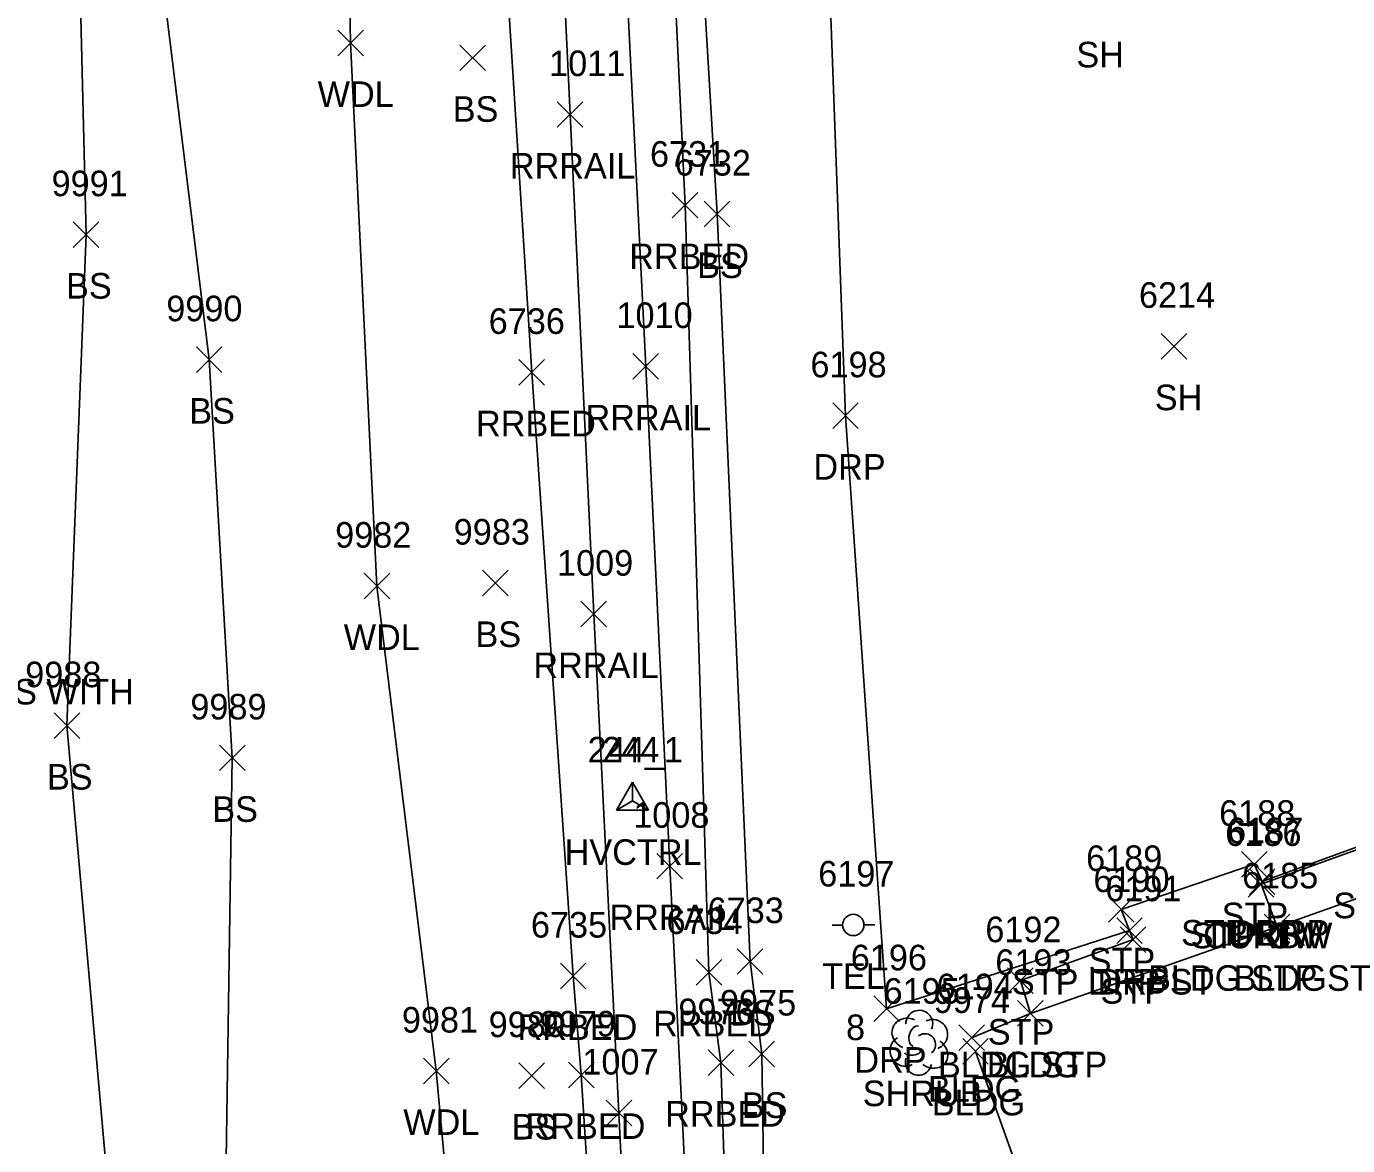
# Model space of a CAD drawing. Extents: x 1769141 to 1770817, y 735471 to 742405.
# Drawn here: x 1770145.7 to 1770248.9, y 740504.9 to 740592.3 of the extents above; entities that cross this region are included whole.
import ezdxf

# ---------------------------------------------------------------- set-up
doc = ezdxf.new("R2010")
doc.units = 0
for name, color, linetype in [('C_A', 7, 'Continuous'), ('C_I', 7, 'Continuous'), ('CPSM', 7, 'Continuous'), ('L_A', 7, 'Continuous'), ('L_I', 7, 'Continuous'), ('L_TIC', 7, 'Continuous'), ('LAWA', 7, 'Continuous'), ('LBC', 7, 'Continuous'), ('LBF', 7, 'Continuous'), ('LELB', 7, 'Continuous'), ('LSH', 7, 'Continuous'), ('R_A', 7, 'Continuous'), ('R_C', 7, 'Continuous'), ('R_I', 7, 'Continuous'), ('R_TIC', 7, 'Continuous'), ('RC', 7, 'Continuous'), ('RDP', 7, 'Continuous'), ('RR', 7, 'Continuous'), ('RRB', 7, 'Continuous'), ('U_A', 7, 'Continuous'), ('U_C', 7, 'Continuous'), ('U_I', 7, 'Continuous'), ('UP', 7, 'Continuous')]:
    doc.layers.add(name, color=color, linetype=linetype)

msp = doc.modelspace()

# ---------------------------------------------------------------- linework, layer by layer
at = {"layer": 'CPSM'}
for p, q in [((1770191.81, 740531.11), (1770193.06, 740533.28)), ((1770191.81, 740531.11), (1770193.06, 740533.28)), ((1770194.31, 740531.11), (1770193.06, 740533.28)), ((1770193.06, 740531.83), (1770193.06, 740533.28)), ((1770194.31, 740531.11), (1770193.06, 740533.28)), ((1770193.06, 740531.83), (1770193.06, 740533.28)), ((1770191.81, 740531.11), (1770193.06, 740531.83)), ((1770191.81, 740531.11), (1770193.06, 740531.83)), ((1770193.06, 740531.83), (1770193.06, 740531.83)), ((1770193.06, 740531.83), (1770194.31, 740531.11)), ((1770193.06, 740531.83), (1770193.06, 740531.83)), ((1770193.06, 740531.83), (1770194.31, 740531.11)), ((1770191.81, 740531.11), (1770194.31, 740531.11)), ((1770191.81, 740531.11), (1770194.31, 740531.11))]:
    msp.add_line(p, q, dxfattribs=at)
at = {"layer": 'L_TIC'}
for points in [[(1770170.04, 740590.04), (1770172.04, 740592.04)], [(1770172.04, 740590.04), (1770170.04, 740592.04)], [(1770179.57, 740588.88), (1770181.57, 740590.88)], [(1770181.57, 740588.88), (1770179.57, 740590.88)], [(1770198.66, 740576.68), (1770200.66, 740578.68)], [(1770200.66, 740576.68), (1770198.66, 740578.68)], [(1770149.37, 740575.07), (1770151.37, 740577.07)], [(1770151.37, 740575.07), (1770149.37, 740577.07)], [(1770234.35, 740566.35), (1770236.35, 740568.35)], [(1770236.35, 740566.35), (1770234.35, 740568.35)], [(1770158.99, 740565.3), (1770160.99, 740567.3)], [(1770160.99, 740565.3), (1770158.99, 740567.3)], [(1770172.09, 740547.61), (1770174.09, 740549.61)], [(1770174.09, 740547.61), (1770172.09, 740549.61)], [(1770181.35, 740547.85), (1770183.35, 740549.85)], [(1770183.35, 740547.85), (1770181.35, 740549.85)], [(1770147.88, 740536.71), (1770149.88, 740538.71)], [(1770149.88, 740536.71), (1770147.88, 740538.71)], [(1770160.79, 740534.19), (1770162.79, 740536.19)], [(1770162.79, 740534.19), (1770160.79, 740536.19)], [(1770240.61, 740525.88), (1770242.61, 740527.88)], [(1770242.61, 740525.88), (1770240.61, 740527.88)], [(1770241.15, 740524.31), (1770243.15, 740526.31)], [(1770243.15, 740524.31), (1770241.15, 740526.31)], [(1770241.23, 740524.52), (1770243.23, 740526.52)], [(1770243.23, 740524.52), (1770241.23, 740526.52)], [(1770230.23, 740522.35), (1770232.23, 740524.35)], [(1770232.23, 740522.35), (1770230.23, 740524.35)], [(1770230.87, 740520.7), (1770232.87, 740522.7)], [(1770232.87, 740520.7), (1770230.87, 740522.7)], [(1770242.4, 740520.99), (1770244.4, 740522.99)], [(1770244.4, 740520.99), (1770242.4, 740522.99)], [(1770242.4, 740520.99), (1770244.4, 740522.99)], [(1770244.4, 740520.99), (1770242.4, 740522.99)], [(1770231.15, 740519.99), (1770233.15, 740521.99)], [(1770233.15, 740519.99), (1770231.15, 740521.99)], [(1770201.23, 740518.28), (1770203.23, 740520.28)], [(1770203.23, 740518.28), (1770201.23, 740520.28)], [(1770222.35, 740516.79), (1770224.35, 740518.79)], [(1770224.35, 740516.79), (1770222.35, 740518.79)], [(1770223.13, 740514.23), (1770225.13, 740516.23)], [(1770225.13, 740514.23), (1770223.13, 740516.23)], [(1770223.13, 740514.23), (1770225.13, 740516.23)], [(1770225.13, 740514.23), (1770223.13, 740516.23)], [(1770218.54, 740512.33), (1770220.54, 740514.33)], [(1770220.54, 740512.33), (1770218.54, 740514.33)], [(1770218.84, 740511.26), (1770220.84, 740513.26)], [(1770220.84, 740511.26), (1770218.84, 740513.26)], [(1770202.15, 740511.06), (1770204.15, 740513.06)], [(1770204.15, 740511.06), (1770202.15, 740513.06)], [(1770176.73, 740509.73), (1770178.73, 740511.73)], [(1770178.73, 740509.73), (1770176.73, 740511.73)], [(1770184.17, 740509.37), (1770186.17, 740511.37)], [(1770186.17, 740509.37), (1770184.17, 740511.37)]]:
    msp.add_lwpolyline(points, dxfattribs=at)
at = {"layer": 'LAWA'}
for points in [[(1770171.04, 740591.04), (1770170.45, 740620.93)], [(1770183.2, 740359.32), (1770182.39, 740388.64), (1770182, 740440), (1770181.07, 740474.45), (1770177.73, 740510.73), (1770173.09, 740548.61), (1770171.04, 740591.04)]]:
    msp.add_lwpolyline(points, dxfattribs=at)
at = {"layer": 'LBC'}
for points in [[(1770225.6, 740472.93), (1770279.13, 740491.75), (1770265.37, 740529.79), (1770243.4, 740521.99), (1770224.13, 740515.23), (1770219.54, 740513.33)], [(1770225.27, 740474.05), (1770218.82, 740491.55), (1770226.07, 740494.84), (1770219.84, 740512.26)]]:
    msp.add_lwpolyline(points, dxfattribs=at)
at = {"layer": 'LBF'}
msp.add_lwpolyline([(1770243.4, 740521.99), (1770242.15, 740525.31), (1770242.23, 740525.52), (1770241.61, 740526.88), (1770231.23, 740523.35), (1770231.87, 740521.7), (1770232.15, 740520.99), (1770223.35, 740517.79), (1770224.13, 740515.23)], dxfattribs=at)
at = {"layer": 'LELB'}
for points in [[(1770192.19, 740728.03), (1770194.1, 740678.66), (1770196.52, 740630.7), (1770199.66, 740577.68), (1770202.23, 740519.28)], [(1770167.07, 740363.73), (1770164.66, 740417.49), (1770161.1, 740489.86), (1770161.79, 740535.19), (1770159.99, 740566.3), (1770156.13, 740597.65), (1770156.76, 740657.51)], [(1770157.79, 740363.98), (1770157.08, 740418.77), (1770153.72, 740483.23), (1770148.88, 740537.71), (1770150.37, 740576.07), (1770149.56, 740610.02), (1770143.11, 740653.52)], [(1770203.15, 740512.06), (1770202.23, 740519.28)], [(1770211.26, 740331.68), (1770209.42, 740362.93), (1770207.28, 740387.78), (1770204.09, 740437.38), (1770203.7, 740475.25), (1770203.15, 740512.06)]]:
    msp.add_lwpolyline(points, dxfattribs=at)
at = {"layer": 'LSH'}
msp.add_line((1770215.4, 740512.98), (1770215.4, 740512.98), dxfattribs=at)
msp.add_line((1770215.4, 740512.98), (1770215.4, 740512.98), dxfattribs=at)
msp.add_arc((1770215.45, 740514.42), 1.05, 335.5272, 180.9563, dxfattribs=at)
for centre, major_axis, ratio, start_param, end_param in [((1770214.61, 740513.65), (1.21, -0.51), 0.895232, 1.570796, 4.712389), ((1770215.19, 740513.44), (-0.208, -0.792), 0.645439, 3.141593, 6.283185), ((1770216.44, 740513.56), (-1.14, -0.48), 0.949671, 1.570796, 4.712389), ((1770214.32, 740512.27), (0.58, -1.04), 0.959034, 3.141593, 6.283185), ((1770215.9, 740512.81), (-0.5, 0.667), 0.989748, 3.141593, 6.283185), ((1770214.94, 740512.23), (-0.625, -0.083), 0.423636, 0, 3.141593), ((1770216.4, 740512.15), (-1.09, 0.79), 0.841452, 1.570796, 4.712389), ((1770215.4, 740511.48), (0.26, 1.06), 0.942809, 1.570796, 4.712389)]:
    msp.add_ellipse(centre, major_axis=major_axis, ratio=ratio, start_param=start_param, end_param=end_param, dxfattribs=at)
at = {"layer": 'R_TIC'}
for points in [[(1770187.18, 740584.45), (1770189.18, 740586.45)], [(1770189.18, 740584.45), (1770187.18, 740586.45)], [(1770196.16, 740577.37), (1770198.16, 740579.37)], [(1770198.16, 740577.37), (1770196.16, 740579.37)], [(1770184.18, 740564.31), (1770186.18, 740566.31)], [(1770186.18, 740564.31), (1770184.18, 740566.31)], [(1770193.09, 740564.77), (1770195.09, 740566.77)], [(1770195.09, 740564.77), (1770193.09, 740566.77)], [(1770208.69, 740560.92), (1770210.69, 740562.92)], [(1770210.69, 740560.92), (1770208.69, 740562.92)], [(1770189.02, 740545.42), (1770191.02, 740547.42)], [(1770191.02, 740545.42), (1770189.02, 740547.42)], [(1770194.96, 740525.73), (1770196.96, 740527.73)], [(1770196.96, 740525.73), (1770194.96, 740527.73)], [(1770241.15, 740524.31), (1770243.15, 740526.31)], [(1770243.15, 740524.31), (1770241.15, 740526.31)], [(1770241.23, 740524.52), (1770243.23, 740526.52)], [(1770243.23, 740524.52), (1770241.23, 740526.52)], [(1770230.87, 740520.7), (1770232.87, 740522.7)], [(1770232.87, 740520.7), (1770230.87, 740522.7)], [(1770198.02, 740517.43), (1770200.02, 740519.43)], [(1770200.02, 740517.43), (1770198.02, 740519.43)], [(1770187.42, 740517.15), (1770189.42, 740519.15)], [(1770189.42, 740517.15), (1770187.42, 740519.15)], [(1770211.9, 740514.59), (1770213.9, 740516.59)], [(1770213.9, 740514.59), (1770211.9, 740516.59)], [(1770198.96, 740510.38), (1770200.96, 740512.38)], [(1770200.96, 740510.38), (1770198.96, 740512.38)], [(1770188.05, 740509.42), (1770190.05, 740511.42)], [(1770190.05, 740509.42), (1770188.05, 740511.42)], [(1770190.99, 740506.45), (1770192.99, 740508.45)], [(1770192.99, 740506.45), (1770190.99, 740508.45)]]:
    msp.add_lwpolyline(points, dxfattribs=at)
at = {"layer": 'RC'}
msp.add_lwpolyline([(1770264.56, 740533.39), (1770242.15, 740525.31)], dxfattribs=at)
at = {"layer": 'RDP'}
for points in [[(1770231.87, 740521.7), (1770212.9, 740515.59), (1770209.69, 740561.92), (1770208.23, 740601.59), (1770205.85, 740650.74), (1770204.34, 740686.71), (1770221.92, 740690.38), (1770237.17, 740650.12), (1770253.28, 740606.93), (1770255.09, 740605.92), (1770259.2, 740607.52)], [(1770273.86, 740568.65), (1770270.48, 740567.47), (1770269.17, 740565.33), (1770278.8, 740539.72), (1770264.83, 740533.77), (1770242.23, 740525.52)]]:
    msp.add_lwpolyline(points, dxfattribs=at)
at = {"layer": 'RR'}
for points in [[(1770197.75, 740390.49), (1770195.85, 740429.49), (1770193.92, 740468.48), (1770191.99, 740507.45), (1770190.02, 740546.42), (1770188.18, 740585.45), (1770186.34, 740624.52), (1770184.35, 740663.53), (1770182.41, 740702.58), (1770181.02, 740730.45), (1770179.25, 740766.27), (1770177.16, 740810.3), (1770173.74, 740877.11), (1770171.32, 740927.71), (1770169.45, 740967.98), (1770167.61, 741006.36), (1770166.54, 741027.4), (1770165.65, 741046.21), (1770163.84, 741084.65), (1770161.66, 741123.76), (1770160.41, 741153.19), (1770158.42, 741192.16), (1770156.87, 741228.02)], [(1770203.66, 740370.75), (1770201.77, 740409.67), (1770199.78, 740448.72), (1770197.9, 740487.78), (1770195.96, 740526.73), (1770194.09, 740565.77), (1770192.14, 740604.84), (1770190.28, 740643.85), (1770188.29, 740682.87), (1770186.41, 740721.83), (1770184.15, 740770), (1770182.62, 740801.29), (1770179.63, 740862.12), (1770176.86, 740918.91), (1770174.1, 740971.71), (1770172.22, 741013.51), (1770171.36, 741030.47), (1770170.33, 741051.22), (1770168.96, 741081.09), (1770166.99, 741119.98), (1770165.66, 741147.29), (1770164.69, 741163.32), (1770164.28, 741173.16), (1770162.44, 741212.29)]]:
    msp.add_lwpolyline(points, dxfattribs=at)
at = {"layer": 'RRB'}
for points in [[(1770189.63, 740726.96), (1770192.08, 740679.1), (1770194.72, 740629.94), (1770197.16, 740578.37), (1770199.02, 740518.43)], [(1770188.42, 740518.15), (1770185.18, 740565.31), (1770181.91, 740617.11), (1770179.16, 740672.3)], [(1770199.96, 740511.38), (1770199.02, 740518.43)], [(1770189.05, 740510.42), (1770188.42, 740518.15)], [(1770206.67, 740352.7), (1770205.87, 740389.14), (1770202.04, 740437.8), (1770201.12, 740475.3), (1770199.96, 740511.38)], [(1770196.54, 740352.14), (1770194.79, 740388.3), (1770192.65, 740437.18), (1770191.37, 740474.26), (1770189.05, 740510.42)]]:
    msp.add_lwpolyline(points, dxfattribs=at)
at = {"layer": 'UP'}
for p, q in [((1770208.64, 740522.13), (1770209.47, 740522.13)), ((1770210.3, 740522.14), (1770210.3, 740522.14)), ((1770211.97, 740522.14), (1770211.13, 740522.14)), ((1770211.13, 740522.14), (1770211.13, 740522.14)), ((1770211.97, 740522.14), (1770211.97, 740522.14))]:
    msp.add_line(p, q, dxfattribs=at)
msp.add_circle((1770210.3, 740522.14), 0.833, dxfattribs=at)

# ---------------------------------------------------------------- texts
at = {"layer": 'C_A'}
msp.add_text('HVCTRL', height=2, dxfattribs=at).set_placement((1770187.75, 740526.83))
msp.add_text('HVCTRL', height=2, dxfattribs=at).set_placement((1770187.75, 740526.83))
at = {"layer": 'C_I'}
for s, p in [('244_1', (1770189.55, 740534.83)), ('244', (1770190.69, 740534.83))]:
    msp.add_text(s, height=2, dxfattribs=at).set_placement(p)
at = {"layer": 'L_A'}
for s, p in [('SH', (1770227.72, 740589.13)), ('WDL', (1770168.46, 740586.04)), ('BS', (1770179.01, 740584.88)), ('BS', (1770198.1, 740572.68)), ('BS', (1770148.81, 740571.07)), ('SH', (1770233.84, 740562.35)), ('BS', (1770158.43, 740561.3)), ('WDL', (1770170.5, 740543.61)), ('BS', (1770180.79, 740543.85)), ('BS', (1770147.32, 740532.71)), ('BS', (1770160.23, 740530.19)), ('SHRUB', (1770247.78, 740522.66)), ('STP', (1770239.07, 740521.88)), ('STP DRP', (1770235.9, 740520.52)), ('STP CW', (1770236.65, 740520.31)), ('STP', (1770228.68, 740518.35)), ('STP DRP ST', (1770222.68, 740516.7)), ('BLDG STP ST', (1770233.32, 740516.99)), ('BLDG', (1770240, 740516.99)), ('STP', (1770229.61, 740515.99)), ('BS', (1770200.67, 740514.28)), ('STP', (1770220.8, 740512.79)), ('BLDG STP', (1770216.91, 740510.23)), ('BLDG', (1770220.72, 740510.23)), ('BLDG', (1770216.13, 740508.33)), ('BS', (1770201.59, 740507.06)), ('SHRUB', (1770211.03, 740507.98)), ('BLDG', (1770216.43, 740507.26)), ('WDL', (1770175.15, 740505.73)), ('BS', (1770183.61, 740505.37))]:
    msp.add_text(s, height=2, dxfattribs=at).set_placement(p)
at = {"layer": 'L_I'}
for s, p in [('6732', (1770196.35, 740580.68)), ('9991', (1770147.68, 740579.07)), ('6214', (1770232.61, 740570.35)), ('9990', (1770156.64, 740569.3)), ('9982', (1770169.83, 740551.61)), ('9983', (1770179.09, 740551.85)), ('9988', (1770145.62, 740540.71)), ('9989', (1770158.52, 740538.19)), ('6188', (1770238.87, 740529.88)), ('6186', (1770239.35, 740528.31)), ('6187', (1770239.49, 740528.52)), ('6189', (1770228.48, 740526.35)), ('6190', (1770229.05, 740524.7)), ('6185', (1770240.66, 740524.99)), ('6185', (1770240.66, 740524.99)), ('6191', (1770229.98, 740523.99)), ('6733', (1770198.92, 740522.28)), ('6192', (1770220.61, 740520.79)), ('6193', (1770221.39, 740518.23)), ('6193', (1770221.39, 740518.23)), ('6195', (1770212.66, 740515.98)), ('6194', (1770216.8, 740516.33)), ('9975', (1770199.89, 740515.06)), ('9974', (1770216.58, 740515.26)), ('9981', (1770175.04, 740513.73)), ('9980', (1770181.82, 740513.37))]:
    msp.add_text(s, height=2, dxfattribs=at).set_placement(p)
at = {"layer": 'R_A'}
for s, p in [('RRRAIL', (1770183.47, 740580.45)), ('RRBED', (1770192.8, 740573.37)), ('RRRAIL', (1770189.38, 740560.77)), ('RRBED', (1770180.83, 740560.31)), ('DRP', (1770207.18, 740556.92)), ('RRRAIL', (1770185.31, 740541.42)), ('RRRAIL', (1770191.25, 740521.73)), ('DRP', (1770239.72, 740520.52)), ('CURBW', (1770237.61, 740520.31)), ('DRP', (1770229.36, 740516.7)), ('RRBED', (1770194.66, 740513.43)), ('RRBED', (1770184.07, 740513.15)), ('DRP', (1770210.38, 740510.59)), ('RRBED', (1770195.6, 740506.38)), ('RRBED', (1770184.7, 740505.42))]:
    msp.add_text(s, height=2, dxfattribs=at).set_placement(p)
at = {"layer": 'R_C'}
msp.add_text('ROW OF WOODEN GUIDE POSTS WITH', height=2, dxfattribs=at).set_placement((1770103.45, 740539.36))
at = {"layer": 'R_I'}
for s, p in [('1011', (1770186.54, 740588.45)), ('6731', (1770194.42, 740581.37)), ('6736', (1770181.82, 740568.31)), ('1010', (1770191.8, 740568.77)), ('6198', (1770206.95, 740564.92)), ('1009', (1770187.16, 740549.42)), ('1008', (1770193.11, 740529.73)), ('6186', (1770239.35, 740528.31)), ('6187', (1770239.49, 740528.52)), ('6190', (1770229.05, 740524.7)), ('6735', (1770185.12, 740521.15)), ('6734', (1770195.71, 740521.43)), ('6196', (1770210.1, 740518.59)), ('9976', (1770196.64, 740514.38)), ('9979', (1770185.79, 740513.42)), ('1007', (1770189.14, 740510.45))]:
    msp.add_text(s, height=2, dxfattribs=at).set_placement(p)
at = {"layer": 'U_A'}
msp.add_text('TEL', height=2, dxfattribs=at).set_placement((1770207.86, 740517.14))
at = {"layer": 'U_C'}
msp.add_text('8', height=2, dxfattribs=at).set_placement((1770209.73, 740513.14))
at = {"layer": 'U_I'}
msp.add_text('6197', height=2, dxfattribs=at).set_placement((1770207.56, 740525.14))

doc.saveas('drawing.dxf')
